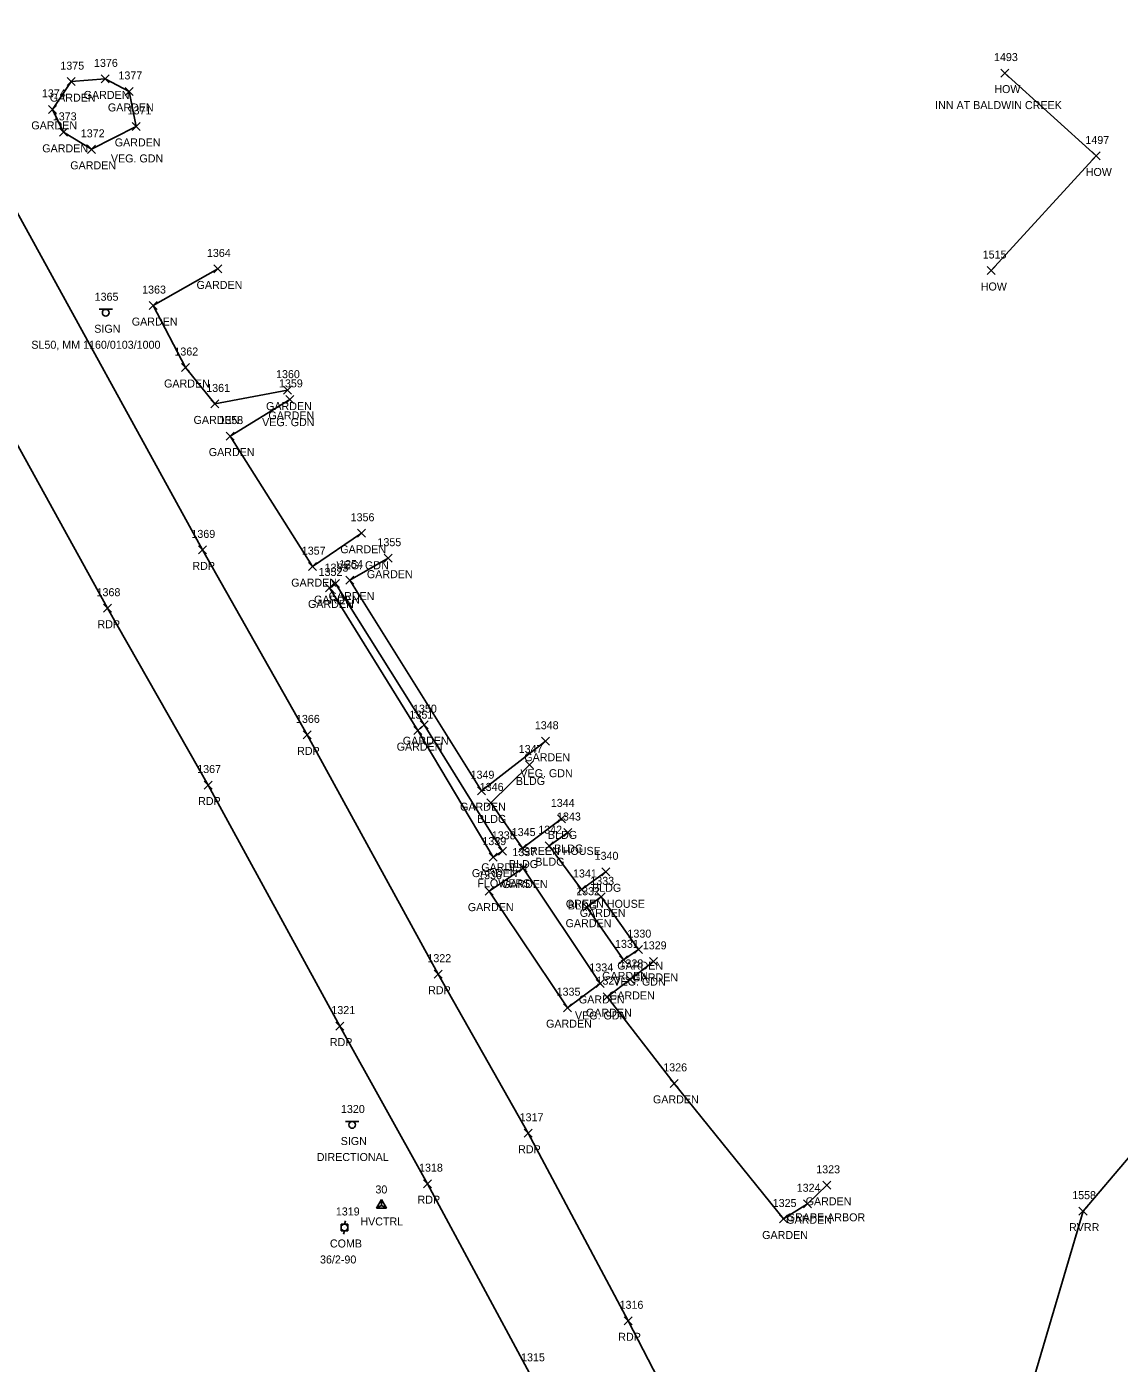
# Model space of a CAD drawing. Extents: x 1496556 to 1498241, y 599216 to 604470.
# Drawn here: x 1496982.4 to 1497255.4, y 603294.3 to 603628.4 of the extents above; entities that cross this region are included whole.
import ezdxf

# ---------------------------------------------------------------- set-up
doc = ezdxf.new("R2010")
doc.units = 0
for name, color, linetype in [('C_A', 7, 'Continuous'), ('C_I', 7, 'Continuous'), ('CPSM', 7, 'Continuous'), ('L_A', 7, 'Continuous'), ('L_C', 7, 'Continuous'), ('L_I', 7, 'Continuous'), ('L_TIC', 7, 'Continuous'), ('LAPB', 7, 'Continuous'), ('LAWE', 7, 'Continuous'), ('LBC', 7, 'Continuous'), ('P_A', 7, 'Continuous'), ('P_I', 7, 'Continuous'), ('P_TIC', 7, 'Continuous'), ('PET', 7, 'Continuous'), ('S_A', 7, 'Continuous'), ('S_C', 7, 'Continuous'), ('S_I', 7, 'Continuous'), ('SSGN', 7, 'Continuous'), ('U_A', 7, 'Continuous'), ('U_C', 7, 'Continuous'), ('U_I', 7, 'Continuous'), ('UP', 7, 'Continuous')]:
    doc.layers.add(name, color=color, linetype=linetype)

msp = doc.modelspace()

# ---------------------------------------------------------------- linework, layer by layer
at = {"layer": 'CPSM'}
for p, q in [((1497069.87, 603333.05), (1497071.12, 603335.22)), ((1497069.87, 603333.05), (1497071.12, 603333.77)), ((1497069.87, 603333.05), (1497072.37, 603333.05)), ((1497072.37, 603333.05), (1497071.12, 603335.22)), ((1497071.12, 603333.77), (1497071.12, 603335.22)), ((1497071.12, 603333.77), (1497071.12, 603333.77)), ((1497071.12, 603333.77), (1497072.37, 603333.05))]:
    msp.add_line(p, q, dxfattribs=at)
at = {"layer": 'L_TIC'}
for points in [[(1497001, 603614.37), (1497003, 603616.37)], [(1497003, 603614.37), (1497001, 603616.37)], [(1497225.83, 603615.83), (1497227.83, 603617.83)], [(1497227.83, 603615.83), (1497225.83, 603617.83)], [(1496992.54, 603613.69), (1496994.54, 603615.69)], [(1496994.54, 603613.69), (1496992.54, 603615.69)], [(1497007.05, 603611.24), (1497009.05, 603613.24)], [(1497009.05, 603611.24), (1497007.05, 603613.24)], [(1497007.05, 603611.24), (1497009.05, 603613.24)], [(1497009.05, 603611.24), (1497007.05, 603613.24)], [(1496987.92, 603606.76), (1496989.92, 603608.76)], [(1496989.92, 603606.76), (1496987.92, 603608.76)], [(1496990.65, 603601.02), (1496992.65, 603603.02)], [(1496992.65, 603601.02), (1496990.65, 603603.02)], [(1497008.77, 603602.5), (1497010.77, 603604.5)], [(1497010.77, 603602.5), (1497008.77, 603604.5)], [(1497008.77, 603602.5), (1497010.77, 603604.5)], [(1497010.77, 603602.5), (1497008.77, 603604.5)], [(1496997.65, 603596.77), (1496999.65, 603598.77)], [(1496999.65, 603596.77), (1496997.65, 603598.77)], [(1497248.67, 603595.11), (1497250.67, 603597.11)], [(1497250.67, 603595.11), (1497248.67, 603597.11)], [(1497029.21, 603566.87), (1497031.21, 603568.87)], [(1497031.21, 603566.87), (1497029.21, 603568.87)], [(1497222.44, 603566.48), (1497224.44, 603568.48)], [(1497224.44, 603566.48), (1497222.44, 603568.48)], [(1497013.02, 603557.71), (1497015.02, 603559.71)], [(1497015.02, 603557.71), (1497013.02, 603559.71)], [(1497021.08, 603542.23), (1497023.08, 603544.23)], [(1497023.08, 603542.23), (1497021.08, 603544.23)], [(1497046.57, 603536.57), (1497048.57, 603538.57)], [(1497048.57, 603536.57), (1497046.57, 603538.57)], [(1497047.17, 603534.26), (1497049.17, 603536.26)], [(1497049.17, 603534.26), (1497047.17, 603536.26)], [(1497028.46, 603533.13), (1497030.46, 603535.13)], [(1497030.46, 603533.13), (1497028.46, 603535.13)], [(1497032.26, 603525.09), (1497034.26, 603527.09)], [(1497034.26, 603525.09), (1497032.26, 603527.09)], [(1497065.12, 603500.8), (1497067.12, 603502.8)], [(1497067.12, 603500.8), (1497065.12, 603502.8)], [(1497071.77, 603494.57), (1497073.77, 603496.57)], [(1497073.77, 603494.57), (1497071.77, 603496.57)], [(1497052.86, 603492.45), (1497054.86, 603494.45)], [(1497054.86, 603492.45), (1497052.86, 603494.45)], [(1497057.06, 603487.13), (1497059.06, 603489.13)], [(1497059.06, 603487.13), (1497057.06, 603489.13)], [(1497058.57, 603488.21), (1497060.57, 603490.21)], [(1497060.57, 603488.21), (1497058.57, 603490.21)], [(1497058.57, 603488.21), (1497060.57, 603490.21)], [(1497060.57, 603488.21), (1497058.57, 603490.21)], [(1497062.2, 603489.09), (1497064.2, 603491.09)], [(1497064.2, 603489.09), (1497062.2, 603491.09)], [(1497079.21, 603451.45), (1497081.21, 603453.45)], [(1497081.21, 603451.45), (1497079.21, 603453.45)], [(1497080.75, 603452.94), (1497082.75, 603454.94)], [(1497082.75, 603452.94), (1497080.75, 603454.94)], [(1497111.1, 603448.81), (1497113.1, 603450.81)], [(1497113.1, 603448.81), (1497111.1, 603450.81)], [(1497107.08, 603442.87), (1497109.08, 603444.87)], [(1497109.08, 603442.87), (1497107.08, 603444.87)], [(1497095.05, 603436.44), (1497097.05, 603438.44)], [(1497097.05, 603436.44), (1497095.05, 603438.44)], [(1497097.4, 603433.39), (1497099.4, 603435.39)], [(1497099.4, 603433.39), (1497097.4, 603435.39)], [(1497115.09, 603429.39), (1497117.09, 603431.39)], [(1497117.09, 603429.39), (1497115.09, 603431.39)], [(1497116.64, 603425.99), (1497118.64, 603427.99)], [(1497118.64, 603425.99), (1497116.64, 603427.99)], [(1497100.35, 603421.3), (1497102.35, 603423.3)], [(1497102.35, 603421.3), (1497100.35, 603423.3)], [(1497100.35, 603421.3), (1497102.35, 603423.3)], [(1497102.35, 603421.3), (1497100.35, 603423.3)], [(1497105.33, 603422.1), (1497107.33, 603424.1)], [(1497107.33, 603422.1), (1497105.33, 603424.1)], [(1497111.95, 603422.69), (1497113.95, 603424.69)], [(1497113.95, 603422.69), (1497111.95, 603424.69)], [(1497098, 603419.84), (1497100, 603421.84)], [(1497100, 603419.84), (1497098, 603421.84)], [(1497105.49, 603417.1), (1497107.49, 603419.1)], [(1497107.49, 603417.1), (1497105.49, 603419.1)], [(1497105.49, 603417.1), (1497107.49, 603419.1)], [(1497107.49, 603417.1), (1497105.49, 603419.1)], [(1497126.12, 603416.17), (1497128.12, 603418.17)], [(1497128.12, 603416.17), (1497126.12, 603418.17)], [(1497096.99, 603411.33), (1497098.99, 603413.33)], [(1497098.99, 603411.33), (1497096.99, 603413.33)], [(1497120.07, 603411.75), (1497122.07, 603413.75)], [(1497122.07, 603411.75), (1497120.07, 603413.75)], [(1497121.42, 603407.32), (1497123.42, 603409.32)], [(1497123.42, 603407.32), (1497121.42, 603409.32)], [(1497124.97, 603409.91), (1497126.97, 603411.91)], [(1497126.97, 603409.91), (1497124.97, 603411.91)], [(1497124.97, 603409.91), (1497126.97, 603411.91)], [(1497126.97, 603409.91), (1497124.97, 603411.91)], [(1497130.56, 603394.16), (1497132.56, 603396.16)], [(1497132.56, 603394.16), (1497130.56, 603396.16)], [(1497134.33, 603396.72), (1497136.33, 603398.72)], [(1497136.33, 603396.72), (1497134.33, 603398.72)], [(1497134.33, 603396.72), (1497136.33, 603398.72)], [(1497136.33, 603396.72), (1497134.33, 603398.72)], [(1497138.08, 603393.78), (1497140.08, 603395.78)], [(1497140.08, 603393.78), (1497138.08, 603395.78)], [(1497124.73, 603388.26), (1497126.73, 603390.26)], [(1497126.73, 603388.26), (1497124.73, 603390.26)], [(1497124.73, 603388.26), (1497126.73, 603390.26)], [(1497126.73, 603388.26), (1497124.73, 603390.26)], [(1497132.26, 603389.26), (1497134.26, 603391.26)], [(1497134.26, 603389.26), (1497132.26, 603391.26)], [(1497126.51, 603384.95), (1497128.51, 603386.95)], [(1497128.51, 603384.95), (1497126.51, 603386.95)], [(1497116.54, 603382.2), (1497118.54, 603384.2)], [(1497118.54, 603382.2), (1497116.54, 603384.2)], [(1497143.25, 603363.28), (1497145.25, 603365.28)], [(1497145.25, 603363.28), (1497143.25, 603365.28)], [(1497181.41, 603337.8), (1497183.41, 603339.8)], [(1497183.41, 603337.8), (1497181.41, 603339.8)], [(1497176.54, 603333.19), (1497178.54, 603335.19)], [(1497178.54, 603333.19), (1497176.54, 603335.19)], [(1497245.38, 603331.34), (1497247.38, 603333.34)], [(1497247.38, 603331.34), (1497245.38, 603333.34)], [(1497170.54, 603329.38), (1497172.54, 603331.38)], [(1497172.54, 603329.38), (1497170.54, 603331.38)]]:
    msp.add_lwpolyline(points, dxfattribs=at)
at = {"layer": 'LAPB'}
for points in [[(1497009.77, 603603.5), (1496998.65, 603597.77), (1496991.65, 603602.02), (1496988.92, 603607.76), (1496993.54, 603614.69), (1497002, 603615.37), (1497008.05, 603612.24)], [(1497009.77, 603603.5), (1497008.05, 603612.24)], [(1497047.57, 603537.57), (1497029.46, 603534.13), (1497022.08, 603543.23), (1497014.02, 603558.71), (1497030.21, 603567.87)], [(1497066.12, 603501.8), (1497053.86, 603493.45), (1497033.26, 603526.09), (1497048.17, 603535.26)], [(1497112.1, 603449.81), (1497096.05, 603437.44), (1497063.2, 603490.09), (1497072.77, 603495.57)], [(1497101.35, 603422.3), (1497099, 603420.84), (1497080.21, 603452.45), (1497058.06, 603488.13), (1497059.57, 603489.21)], [(1497101.35, 603422.3), (1497081.75, 603453.94), (1497059.57, 603489.21)], [(1497125.73, 603389.26), (1497117.54, 603383.2), (1497097.99, 603412.33), (1497106.49, 603418.1)], [(1497125.73, 603389.26), (1497106.49, 603418.1)], [(1497135.33, 603397.72), (1497131.56, 603395.16), (1497122.42, 603408.32), (1497125.97, 603410.91)], [(1497135.33, 603397.72), (1497125.97, 603410.91)], [(1497182.41, 603338.8), (1497177.54, 603334.19), (1497171.54, 603330.38), (1497144.25, 603364.28), (1497127.51, 603385.95), (1497133.26, 603390.26), (1497139.08, 603394.78)]]:
    msp.add_lwpolyline(points, dxfattribs=at)
at = {"layer": 'LAWE'}
msp.add_lwpolyline([(1497189.81, 603091.49), (1497191.67, 603112.98), (1497209.98, 603150.46), (1497214.03, 603174.34), (1497209.01, 603206.37), (1497211.24, 603222.01), (1497227.45, 603268.03), (1497246.38, 603332.34), (1497269.89, 603360.04), (1497296.95, 603397.6), (1497313.57, 603422.44), (1497323.64, 603438.94), (1497334.8, 603445.38), (1497344.77, 603450.19), (1497370.1, 603467.8), (1497419.49, 603471.31), (1497456.04, 603468.84), (1497488.04, 603460.85), (1497518.38, 603461.84), (1497564.45, 603467.31)], dxfattribs=at)
at = {"layer": 'LBC'}
for points in [[(1497226.83, 603616.83), (1497249.67, 603596.11), (1497223.44, 603567.48)], [(1497116.09, 603430.39), (1497106.33, 603423.1), (1497098.4, 603434.39), (1497108.08, 603443.87)], [(1497127.12, 603417.17), (1497121.07, 603412.75), (1497112.95, 603423.69), (1497117.64, 603426.99)]]:
    msp.add_lwpolyline(points, dxfattribs=at)
at = {"layer": 'P_TIC'}
for points in [[(1497025.34, 603496.64), (1497027.34, 603498.64)], [(1497027.34, 603496.64), (1497025.34, 603498.64)], [(1497001.63, 603482.06), (1497003.63, 603484.06)], [(1497003.63, 603482.06), (1497001.63, 603484.06)], [(1497051.51, 603450.39), (1497053.51, 603452.39)], [(1497053.51, 603450.39), (1497051.51, 603452.39)], [(1497026.78, 603437.86), (1497028.78, 603439.86)], [(1497028.78, 603437.86), (1497026.78, 603439.86)], [(1497084.25, 603390.58), (1497086.25, 603392.58)], [(1497086.25, 603390.58), (1497084.25, 603392.58)], [(1497059.69, 603377.6), (1497061.69, 603379.6)], [(1497061.69, 603377.6), (1497059.69, 603379.6)], [(1497106.74, 603350.81), (1497108.74, 603352.81)], [(1497108.74, 603350.81), (1497106.74, 603352.81)], [(1497081.6, 603338.21), (1497083.6, 603340.21)], [(1497083.6, 603338.21), (1497081.6, 603340.21)], [(1497131.76, 603303.93), (1497133.76, 603305.93)], [(1497133.76, 603303.93), (1497131.76, 603305.93)]]:
    msp.add_lwpolyline(points, dxfattribs=at)
at = {"layer": 'PET'}
for points in [[(1497200.78, 603168.36), (1497190.31, 603189.95), (1497178.56, 603214.16), (1497156.38, 603259.17), (1497132.76, 603304.93), (1497107.74, 603351.81), (1497085.25, 603391.58), (1497052.51, 603451.39), (1497026.34, 603497.64), (1496978.11, 603585.44), (1496929.41, 603673.01), (1496891.52, 603741.51), (1496859.85, 603799.39), (1496832.17, 603849.95), (1496783.86, 603937.37), (1496736.46, 604023.53), (1496687.77, 604111.18), (1496657.13, 604166.72), (1496622.36, 604229.38), (1496597.22, 604275.47)], [(1497183.49, 603131.83), (1497176.45, 603149.42), (1497165.78, 603173.58), (1497153.07, 603202.24), (1497131.76, 603246.13), (1497108.09, 603291.8), (1497082.6, 603339.21), (1497060.69, 603378.6), (1497027.78, 603438.86), (1497002.63, 603483.06), (1496952.93, 603573.18), (1496904.09, 603661), (1496858.14, 603744.51), (1496836.02, 603785.33), (1496807.5, 603837.5), (1496759.38, 603924.22), (1496712.33, 604009.42), (1496662.89, 604098.73), (1496632.3, 604154.09), (1496599.03, 604214.45), (1496572.34, 604262.99)]]:
    msp.add_lwpolyline(points, dxfattribs=at)
at = {"layer": 'SSGN'}
for p, q in [((1497000.53, 603557.78), (1497003.86, 603557.78)), ((1497002.17, 603556.94), (1497002.17, 603556.94)), ((1497062.12, 603354.72), (1497065.45, 603354.72)), ((1497063.76, 603353.89), (1497063.76, 603353.89))]:
    msp.add_line(p, q, dxfattribs=at)
for centre in [(1497002.17, 603556.94), (1497063.76, 603353.89)]:
    msp.add_circle(centre, 0.833, dxfattribs=at)
at = {"layer": 'UP'}
for p, q in [((1497060.98, 603327.43), (1497060.98, 603329.09)), ((1497060.98, 603329.09), (1497062.65, 603329.09)), ((1497062.07, 603329.93), (1497061.82, 603329.09)), ((1497062.65, 603329.09), (1497062.65, 603327.43)), ((1497062.65, 603327.43), (1497060.98, 603327.43)), ((1497061.57, 603326.59), (1497061.82, 603327.43)), ((1497061.82, 603328.26), (1497061.82, 603328.26))]:
    msp.add_line(p, q, dxfattribs=at)
msp.add_circle((1497061.82, 603328.26), 0.833, dxfattribs=at)

# ---------------------------------------------------------------- texts
at = {"layer": 'C_A'}
msp.add_text('HVCTRL', height=2, dxfattribs=at).set_placement((1497065.81, 603328.77))
at = {"layer": 'C_I'}
msp.add_text('30', height=2, dxfattribs=at).set_placement((1497069.57, 603336.77))
at = {"layer": 'L_A'}
for s, p in [('HOW', (1497224.22, 603611.83)), ('GARDEN', (1496988.21, 603609.69)), ('GARDEN', (1496996.67, 603610.37)), ('GARDEN', (1497002.72, 603607.24)), ('GARDEN', (1497002.72, 603607.24)), ('GARDEN', (1496983.59, 603602.76)), ('GARDEN', (1497004.44, 603598.5)), ('GARDEN', (1497004.44, 603598.5)), ('GARDEN', (1496986.32, 603597.02)), ('GARDEN', (1496993.32, 603592.77)), ('HOW', (1497247.06, 603591.11)), ('GARDEN', (1497024.88, 603562.87)), ('HOW', (1497220.83, 603562.48)), ('GARDEN', (1497008.69, 603553.71)), ('GARDEN', (1497016.75, 603538.23)), ('GARDEN', (1497042.24, 603532.57)), ('GARDEN', (1497024.13, 603529.13)), ('GARDEN', (1497042.84, 603530.26)), ('GARDEN', (1497027.93, 603521.09)), ('GARDEN', (1497060.79, 603496.8)), ('GARDEN', (1497067.44, 603490.57)), ('GARDEN', (1497048.53, 603488.45)), ('GARDEN', (1497054.24, 603484.21)), ('GARDEN', (1497054.24, 603484.21)), ('GARDEN', (1497057.87, 603485.09)), ('GARDEN', (1497052.73, 603483.13)), ('GARDEN', (1497074.88, 603447.45)), ('GARDEN', (1497076.42, 603448.94)), ('GARDEN', (1497106.76, 603444.81)), ('BLDG', (1497104.67, 603438.87)), ('GARDEN', (1497090.72, 603432.44)), ('BLDG', (1497094.99, 603429.39)), ('BLDG', (1497112.68, 603425.39)), ('BLDG', (1497114.23, 603421.99)), ('GARDEN', (1497096.02, 603417.3)), ('GARDEN', (1497096.02, 603417.3)), ('BLDG', (1497102.93, 603418.1)), ('BLDG', (1497109.54, 603418.69)), ('GARDEN', (1497093.67, 603415.84)), ('GARDEN', (1497101.16, 603413.1)), ('GARDEN', (1497101.16, 603413.1)), ('BLDG', (1497123.71, 603412.17)), ('GARDEN', (1497092.66, 603407.33)), ('BLDG', (1497117.66, 603407.75)), ('GARDEN', (1497120.64, 603405.91)), ('GARDEN', (1497120.64, 603405.91)), ('GARDEN', (1497117.09, 603403.32)), ('GARDEN', (1497130, 603392.72)), ('GARDEN', (1497130, 603392.72)), ('GARDEN', (1497126.23, 603390.16)), ('GARDEN', (1497133.75, 603389.78)), ('GARDEN', (1497120.4, 603384.26)), ('GARDEN', (1497120.4, 603384.26)), ('GARDEN', (1497127.93, 603385.26)), ('GARDEN', (1497122.17, 603380.95)), ('GARDEN', (1497112.21, 603378.2)), ('GARDEN', (1497138.92, 603359.28)), ('GARDEN', (1497177.08, 603333.8)), ('GARDEN', (1497172.21, 603329.19)), ('RVRR', (1497242.89, 603327.34)), ('GARDEN', (1497166.21, 603325.38))]:
    msp.add_text(s, height=2, dxfattribs=at).set_placement(p)
at = {"layer": 'L_C'}
for s, p in [('INN AT BALDWIN CREEK', (1497209.43, 603607.83)), ('VEG. GDN', (1497003.47, 603594.5)), ('VEG. GDN', (1497003.47, 603594.5)), ('VEG. GDN', (1497041.26, 603528.57)), ('VEG. GDN', (1497059.82, 603492.8)), ('VEG. GDN', (1497105.79, 603440.81)), ('GREEN HOUSE', (1497106.12, 603421.39)), ('FLOWERS', (1497095.05, 603413.3)), ('FLOWERS', (1497095.05, 603413.3)), ('GREEN HOUSE', (1497117.15, 603408.17)), ('VEG. GDN', (1497129.03, 603388.72)), ('VEG. GDN', (1497129.03, 603388.72)), ('VEG. GDN', (1497119.43, 603380.26)), ('VEG. GDN', (1497119.43, 603380.26)), ('GRAPE ARBOR', (1497172.34, 603329.8))]:
    msp.add_text(s, height=2, dxfattribs=at).set_placement(p)
at = {"layer": 'L_I'}
for s, p in [('1375', (1496990.84, 603617.69)), ('1376', (1496999.25, 603618.37)), ('1493', (1497224.14, 603619.83)), ('1377', (1497005.36, 603615.24)), ('1377', (1497005.36, 603615.24)), ('1374', (1496986.23, 603610.76)), ('1373', (1496988.95, 603605.02)), ('1371', (1497007.65, 603606.5)), ('1371', (1497007.65, 603606.5)), ('1372', (1496995.95, 603600.77)), ('1497', (1497246.98, 603599.11)), ('1364', (1497027.47, 603570.87)), ('1515', (1497221.32, 603570.48)), ('1363', (1497011.28, 603561.71)), ('1362', (1497019.34, 603546.23)), ('1360', (1497044.74, 603540.57)), ('1359', (1497045.47, 603538.26)), ('1361', (1497027.29, 603537.13)), ('1358', (1497030.57, 603529.09)), ('1356', (1497063.38, 603504.8)), ('1355', (1497070.08, 603498.57)), ('1357', (1497051.17, 603496.45)), ('1352', (1497055.37, 603491.13)), ('1353', (1497056.87, 603492.21)), ('1353', (1497056.87, 603492.21)), ('1354', (1497060.51, 603493.09)), ('1351', (1497078.08, 603455.45)), ('1350', (1497078.97, 603456.94)), ('1348', (1497109.4, 603452.81)), ('1347', (1497105.38, 603446.87)), ('1349', (1497093.35, 603440.44)), ('1346', (1497095.65, 603437.39)), ('1344', (1497113.4, 603433.39)), ('1343', (1497114.95, 603429.99)), ('1339', (1497096.3, 603423.84)), ('1338', (1497098.66, 603425.3)), ('1338', (1497098.66, 603425.3)), ('1345', (1497103.64, 603426.1)), ('1342', (1497110.26, 603426.69)), ('1337', (1497103.8, 603421.1)), ('1337', (1497103.8, 603421.1)), ('1340', (1497124.34, 603420.17)), ('1336', (1497095.24, 603415.33)), ('1341', (1497118.94, 603415.75)), ('1333', (1497123.27, 603413.91)), ('1333', (1497123.27, 603413.91)), ('1332', (1497119.73, 603411.32)), ('1330', (1497132.55, 603400.72)), ('1330', (1497132.55, 603400.72)), ('1331', (1497129.44, 603398.16)), ('1329', (1497136.38, 603397.78)), ('1334', (1497123.04, 603392.26)), ('1334', (1497123.04, 603392.26)), ('1328', (1497130.56, 603393.26)), ('1327', (1497124.81, 603388.95)), ('1335', (1497114.85, 603386.2)), ('1326', (1497141.5, 603367.28)), ('1323', (1497179.72, 603341.8)), ('1324', (1497174.84, 603337.19)), ('1325', (1497168.84, 603333.38)), ('1558', (1497243.68, 603335.34))]:
    msp.add_text(s, height=2, dxfattribs=at).set_placement(p)
at = {"layer": 'P_A'}
for p in [(1497023.83, 603492.64), (1497000.12, 603478.06), (1497050, 603446.39), (1497025.27, 603433.86), (1497082.74, 603386.58), (1497058.18, 603373.6), (1497105.23, 603346.81), (1497080.09, 603334.21), (1497130.25, 603299.93)]:
    msp.add_text('RDP', height=2, dxfattribs=at).set_placement(p)
at = {"layer": 'P_I'}
for s, p in [('1369', (1497023.59, 603500.64)), ('1368', (1496999.89, 603486.06)), ('1366', (1497049.72, 603454.39)), ('1367', (1497025.04, 603441.86)), ('1322', (1497082.56, 603394.58)), ('1321', (1497058.56, 603381.6)), ('1317', (1497105.61, 603354.81)), ('1318', (1497080.47, 603342.21)), ('1316', (1497130.58, 603307.93)), ('1315', (1497105.97, 603294.8))]:
    msp.add_text(s, height=2, dxfattribs=at).set_placement(p)
at = {"layer": 'S_A'}
for p in [(1496999.31, 603551.92), (1497060.9, 603348.87)]:
    msp.add_text('SIGN', height=2, dxfattribs=at).set_placement(p)
at = {"layer": 'S_C'}
for s, p in [('SL50, MM 1160/0103/1000', (1496983.59, 603547.92)), ('DIRECTIONAL', (1497054.91, 603344.87))]:
    msp.add_text(s, height=2, dxfattribs=at).set_placement(p)
at = {"layer": 'S_I'}
for s, p in [('1365', (1496999.41, 603559.92)), ('1320', (1497060.96, 603356.87))]:
    msp.add_text(s, height=2, dxfattribs=at).set_placement(p)
at = {"layer": 'U_A'}
msp.add_text('COMB', height=2, dxfattribs=at).set_placement((1497058.2, 603323.26))
at = {"layer": 'U_C'}
msp.add_text('36/2-90', height=2, dxfattribs=at).set_placement((1497055.73, 603319.26))
at = {"layer": 'U_I'}
msp.add_text('1319', height=2, dxfattribs=at).set_placement((1497059.68, 603331.26))

doc.saveas('drawing.dxf')
